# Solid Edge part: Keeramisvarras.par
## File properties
Author: Türk
Template: iso part.par
Last saved by: Türk
Revision: 5
Application: Solid Edge
Accuracy: 0,990
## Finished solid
Body 1: solid body, 29 faces, 59 edges, 32 vertices.
  Faces by surface: plane 22, cylinder 7
  Edges by curve: line 36, circle 23
Bounding box of the edges (mm): 50.000 x 1240.000 x 70.000, from (-40, -620, -60) to (10, 620, 10).
Cylindrical faces by radius (mm): R4 x2, R6 x1, R10 x4
Planar faces by outward normal: +x 4, +y 5, +z 2, -x 4, -y 5, -z 2
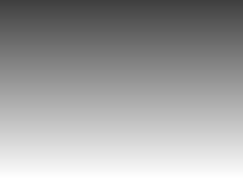
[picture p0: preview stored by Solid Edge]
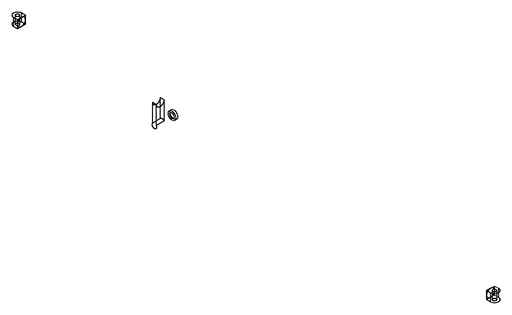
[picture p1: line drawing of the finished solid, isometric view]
